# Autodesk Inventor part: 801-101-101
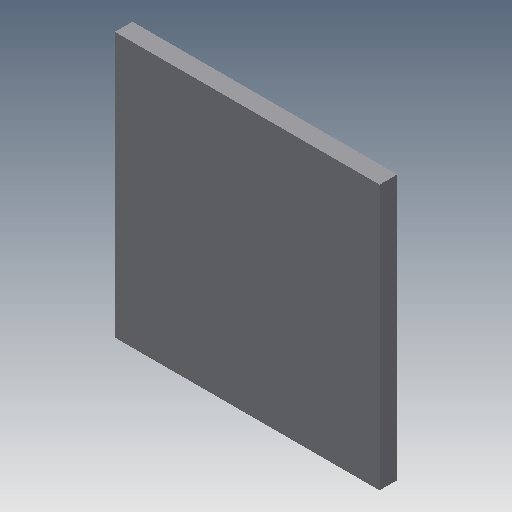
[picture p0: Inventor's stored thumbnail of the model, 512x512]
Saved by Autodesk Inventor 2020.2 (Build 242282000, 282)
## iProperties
Created: 2011-01
Part Number: 801-101-101
Document SubType Name: Modeling
Designer: F.Stasiak
Density: 1 g/cm^3
Material: Ogólny
Appearance: Domyślna
Catalog Web Link: www.expertbooks.pl
Company: Fabian Stasiak CAD Consulting
Manager: www.cadconsulting.pl
Author: F.Stasiak
Subject: Zbiór ćwiczeń. Autodesk Inventor 2020. Kurs Professional
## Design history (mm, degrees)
sketch "Szkic1"
  geometry: L1 (-60, -60)-(60, -60); L2 (60, -60)-(60, 60); L3 (60, 60)-(-60, 60); L4 (-60, 60)-(-60, -60); 3 further points
  constraints: 8 end point, 2 midpoint, 2 parallel, 1 horizontal, 1 horizontal alignment, 1 perpendicular, 1 vertical alignment
  dimensions: "d0" = 120 distance of L1.start L1.end; "d1" = 120 distance of L1.end L2.end (= d0)
extrude "Wyciągnięcie proste1" new body sketch "Szkic1" distance "d2" = 8; taper "d3" = 0 deg
node "Bryła1"
